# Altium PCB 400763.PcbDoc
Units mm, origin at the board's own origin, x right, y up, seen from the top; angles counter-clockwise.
Board outline 17.75 x 49.17 mm, 2 copper layers (Top Layer, Bottom Layer), stack 1.001 mm thick; 10 components, 18 nets, 81 pads, 135 vias.
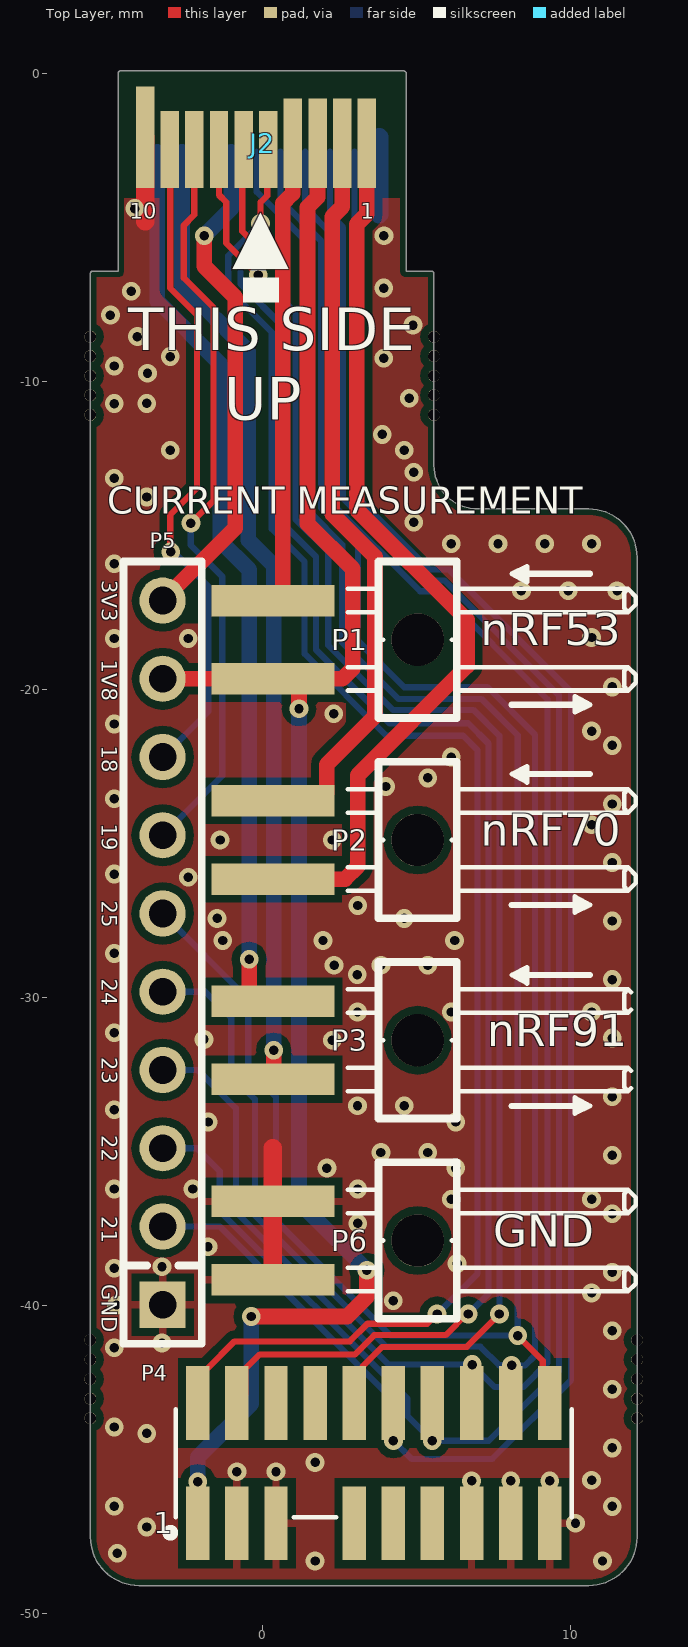
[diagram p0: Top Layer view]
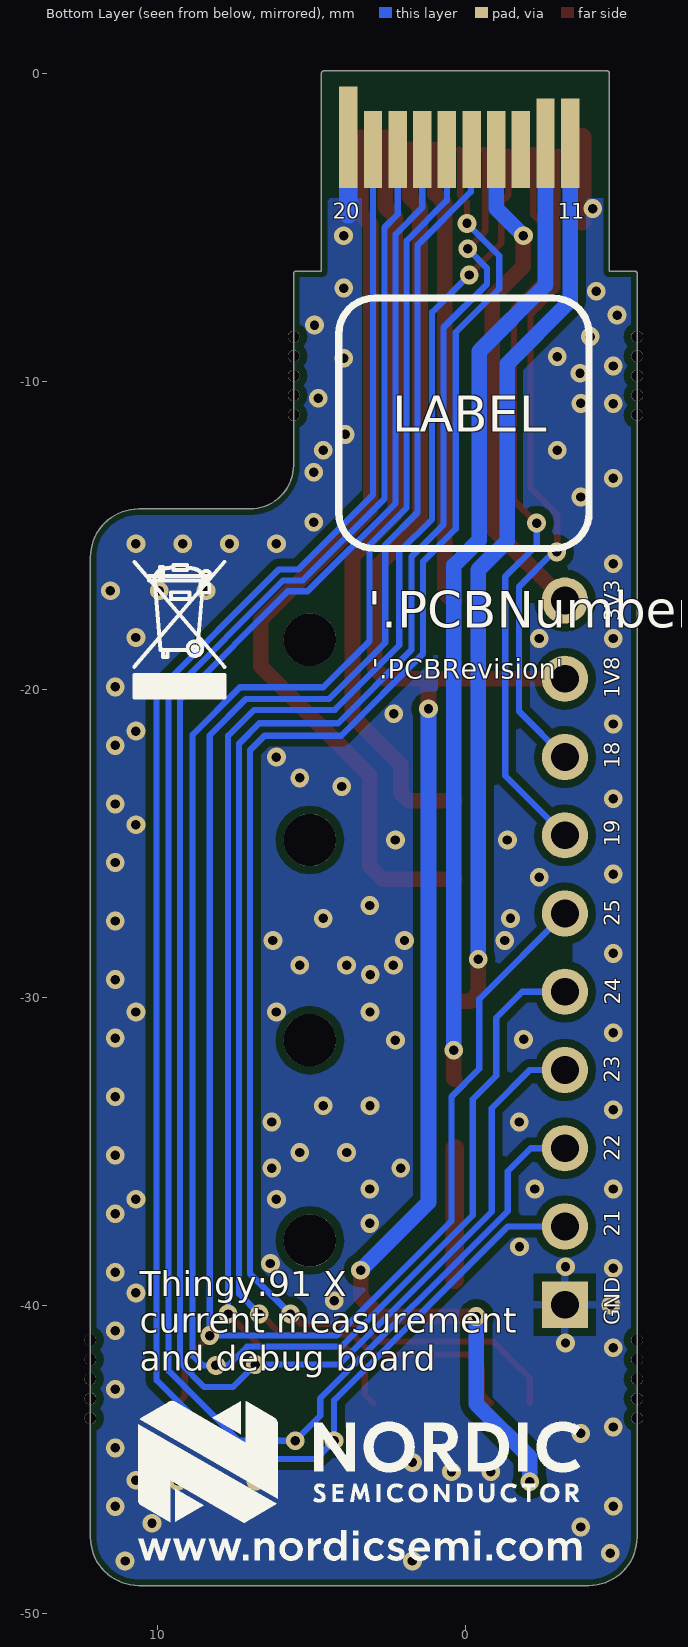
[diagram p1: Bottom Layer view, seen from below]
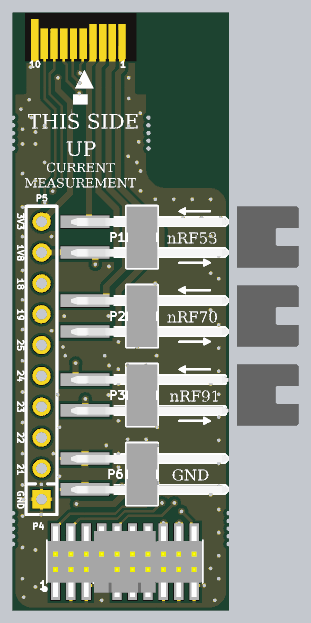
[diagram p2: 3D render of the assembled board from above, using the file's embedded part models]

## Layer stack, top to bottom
Top Solder: solder mask 0.0102, Solder Resist, Dk 3.5
Top Layer: signal copper 0.0356
Dielectric1: core 0.93, FR-4 Halogen Free, Dk 4.8
Bottom Layer: signal copper 0.0356
Bottom Solder: solder mask 0.0102, Solder Resist, Dk 3.5

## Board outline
-5.576,-47.526 -5.577,-12.025 -5.577,-6.5 cw(c-5.5,-6.5) -5.5,-6.423 -4.677,-6.423 -4.677,0 cw(c-4.6,0) -4.6,0.077 4.6,0.077 cw(c4.6,0) 4.677,0 4.677,-6.423 5.5,-6.423 cw(c5.5,-6.5) 5.577,-6.5 5.577,-12.744 5.576,-12.725 ccw(c7,-12.72) 6.995,-14.144 7,-14.143 10.606,-14.143 cw(c10.6,-15.72) 12.176,-15.714 12.177,-47.526 cw(c10.6,-47.52) 10.606,-49.096 10.591,-49.097 -4.006,-49.097 cw(c-4,-47.52)

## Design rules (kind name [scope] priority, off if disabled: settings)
BoardOutlineClearance [Not (HasPad('Free-666') OR OnTopSilkscreen)] p1: gap=0.2 ignorepadtopadclearanceinfootprint=FALSE
Clearance ANT_Clerance [InNet('ANT')] p1: gap=0.127 ignorepadtopadclearanceinfootprint=FALSE except(0: Arc-Hole Track-Hole SMDPad-Hole THPad-Hole Via-Hole Fill-Hole Poly-Hole Region-Hole Text-Hole)
Clearance Polygon_Clearance [(InNamedPolygon('Top_Layer-GND')) or (InNamedPolygon('Bottom_Layer-GND'))] p2: gap=0.254 ignorepadtopadclearanceinfootprint=FALSE
Clearance [All] p3: gap=0.152 ignorepadtopadclearanceinfootprint=FALSE except(0: Arc-Hole Track-Hole SMDPad-Hole THPad-Hole Via-Hole Fill-Hole Poly-Hole Region-Hole Text-Hole)
ComponentClearance [All] p1 off: gap=0.254 collisioncheckmode=3 verticalgap=0.254 showdistances=FALSE
DiffPairsRouting [All] p1: maxlimit=0.15 minlimit=0.15 mostfreqgap=0.15 toplayer_minwidth=0.381 toplayer_maxwidth=0.381 toplayer_prefwidth=0.381 bottomlayer_minwidth=0.381 bottomlayer_maxwidth=0.381 bottomlayer_prefwidth=0.381 maxuncoupledlength=12.7
FabricationTestPointUsage TestPointUsage [All] p1: valid=0 allowmultiple=FALSE
FabricationTestpoint Testpoint [All] p1: side=3 testpointundercomponent=TRUE minsize=1.016 maxsize=2.54 preferedsize=1.524 minholesize=0 maxholesize=1.016 preferedholesize=0.813 testpointgrid=0.025 allowsidetop=TRUE allowsidebottom=TRUE usegrid=TRUE gridtolerance=0
Height [All] p1 off: minheight=0 maxheight=25.4 prefheight=12.7
HoleSize [All] p1: absolutevalues=TRUE maxlimit=5 minlimit=0.305 maxpercent=80.000 minpercent=20.000
MinimumAnnularRing [All] p1 off: minimumring=0.152
PolygonConnect PolygonConnect_1 [isVia and innet(gnd)] p1: connectstyle=Direct reliefconductorwidth=0.254 reliefentries=4 polygonreliefangle="90 Angle" airgapwidth=0.254
PolygonConnect [All] p2: connectstyle=Relief reliefconductorwidth=0.254 reliefentries=4 polygonreliefangle="90 Angle" airgapwidth=0.254
RoutingVias [All] p1: holewidth=0.305 width=0.61 viastyle="Through Hole" minholewidth=0.305 minwidth=0.61 maxholewidth=0.305 maxwidth=0.61
SilkToSolderMaskClearance SilkscreenOverComponentPads [IsPad] p1: minsilkscreentomaskgap=0.125 clearancetoexposedcopper=TRUE
SolderMaskExpansion [All] p1: expansion=0.076 istentingtop=FALSE
Width [All] p1: maxlimit=2.54 minlimit=0.203 preferedwidth=0.381
23 further rules are at their usual default settings.

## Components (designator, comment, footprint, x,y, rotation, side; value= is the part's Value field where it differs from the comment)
J2 "Card Edge, 0.8mm" 10056847-101LF_Mating_Board_Thingy91_v2 0,0.075 r0 top locked
JP1 "Shunt 2.54mm" Shunt_2.54mm_Horizontal 15.4,-20.905 r90 top locked
JP2 "Shunt 2.54mm" Shunt_2.54mm_Horizontal 15.4,-27.407 r90 top locked
JP3 "Shunt 2.54mm" Shunt_2.54mm_Horizontal 15.4,-33.909 r90 top locked
P1 "Pin List 1x2, Angled" LIST_ANG_1x2-SMD-2.54MM 0.555,-18.39 r90 top locked
P2 "Pin List 1x2, Angled" LIST_ANG_1x2-SMD-2.54MM 0.555,-24.892 r90 top locked
P3 "Pin List 1x2, Angled" LIST_ANG_1x2-SMD-2.54MM 0.555,-31.395 r90 top locked
P4 "Pin Header 2x10, 1.27mm, SWD" HDR_2x10-SMD-1.27mm-K-SWD 3.625,-45.125 r0 top locked
P5 "Pin List 1x10" LIST_1x10-NC -3.23,-28.55 r90 top locked
P6 "Pin List 1x2, Angled" LIST_ANG_1x2-SMD-2.54MM 0.555,-37.897 r90 top locked

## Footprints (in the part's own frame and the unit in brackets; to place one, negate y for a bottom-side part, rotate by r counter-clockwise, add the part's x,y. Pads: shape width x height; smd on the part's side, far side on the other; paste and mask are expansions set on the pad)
10056847-101LF_Mating_Board_Thingy91_v2 [mm]
  rect 0.6x2.9 smd paste-1 mask+0.025: 1(3.4,-2.35) 2(2.6,-2.35) 3(1.8,-2.35) 4(1,-2.35)
  rect 0.6x2.5 smd paste-1 mask+0.025: 5(0.2,-2.55) 6(-0.6,-2.55) 7(-1.4,-2.55) 8(-2.2,-2.55) 9(-3,-2.55)
  rect 0.6x3.3 smd paste-1 mask+0.025: 10(-3.8,-2.15)
  rect 0.6x2.9 smd far side paste-1 mask+0.025: 11(-3.4,-2.35) 12(-2.6,-2.35)
  rect 0.6x2.5 smd far side paste-1 mask+0.025: 13(-1.8,-2.55) 14(-1,-2.55) 15(-0.2,-2.55) 16(0.6,-2.55) 17(1.4,-2.55) 18(2.2,-2.55) 19(3,-2.55)
  rect 0.6x3.3 smd far side paste-1 mask+0.025: 20(3.8,-2.15)
HDR_2x10-SMD-1.27mm-K-SWD [mm] "SMT MICRO HEADER, (1,27) .050\" Keying Shroud w/ pin 7 removed"
  rect 0.76x2.4 smd: 1(-5.715,-1.95) 2(-5.715,1.95) 3(-4.445,-1.95) 4(-4.445,1.95) 5(-3.175,-1.95) 6(-3.175,1.95) 8(-1.905,1.95) 9(-0.635,-1.95) 10(-0.635,1.95) 11(0.635,-1.95) 12(0.635,1.95) 13(1.905,-1.95) 14(1.905,1.95) 15(3.175,-1.95) 16(3.175,1.95) 17(4.445,-1.95) 18(4.445,1.95) 19(5.715,-1.95) 20(5.715,1.95)
  silkscreen extent -6.73,-2.38 6.43,1.75, body extent -6.35,-2.92 6.35,2.92, height 6.11
LIST_1x10-NC [mm] "Pin List, 2.54mm through hole"
  rect 1.5x1.5 hole 0.9: 1(-11.43,0)
  round 1.5 hole 0.9: 2(-8.89,0) 3(-6.35,0) 4(-3.81,0) 5(-1.27,0) 6(1.27,0) 7(3.81,0) 8(6.35,0) 9(8.89,0) 10(11.43,0)
  silkscreen extent -12.7,-1.27 12.7,1.27
LIST_ANG_1x2-SMD-2.54MM [mm] "Pin List, 2.54mm, Surface Mount, Angled"
  round 1.7 hole 1.7 unplated: 0(0,-4.496)
  rect 1.02x4 smd: 1(-1.27,0.204) 2(1.27,0.204)
  silkscreen extent -2.54,-11.58 2.54,-2.22, body extent -2.56,-11.61 2.52,1.35, height 3.03
Shunt_2.54mm_Horizontal [mm]
  body extent 0,-2.54 5.03,2.54, height 3.09

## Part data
J2: library part 10056847-101LF_Mating_Board_for_Thingy:91_v2, "0.8mm pitch, dual edge, right angle, SMD, card edge connector", Manufacturer=FCI, Manufacturer Part Number=10056847-101LF, Part number IPS=N.A., Part number NEMS=100500798
JP1 JP2 JP3: library part "SHUNT JUMPER 2.54mm Black Tin", "Shunt Jumper 2.54mm Black, open top", Manufacturer=WCON, Manufacturer Part Number=3710-6001OS0B05, Part number IPS=N.A., Part number NEMS=100500728
P1 P2 P3 P6: library part "Pin List Ang 1x2 SMD, 2.54mm", "Pin List 1x2, 2.54mm (100mil), Right Angled, SMD", Manufacturer=WCON, Manufacturer Part Number=1125B-1102S0Z135CR06, Part number IPS=N.A., Part number NEMS=100500354
P4: library part "Pin Header 2x10 SMD, 1.27mm, KS, SWD (Cabcon)", "Pin Header 2x10, 1.27mm (50mil), SMD, Keying Shroud, Removed Pin 7", Manufacturer=WCON, Manufacturer Part Number=3132-20MS0BK00R5, Part number IPS=N.A., Part number NEMS=100500841,100500280
P5: library part "Pin List 1x10, N.C.", "Pin List 1x10, 2.54mm (100mil)", Manufacturer=N.A., Part number NEMS=100500336

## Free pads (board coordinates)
  round 0.381 hole 0.381 unplated mask+0: 666(-5.576,-43.665) 666(-5.576,-43.03) 666(-5.576,-42.395) 666(-5.576,-41.76) 666(-5.576,-41.125) 666(-5.576,-11.09) 666(-5.576,-10.455) 666(-5.576,-9.82) 666(-5.576,-9.185) 666(-5.576,-8.55) 666(5.577,-11.09) 666(5.577,-10.455) 666(5.577,-9.82) 666(5.577,-9.185) 666(5.577,-8.55) 666(12.176,-43.665) 666(12.176,-43.03) 666(12.176,-42.395) 666(12.176,-41.76) 666(12.176,-41.125)

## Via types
v1: diameter 0.61, hole 0.305, Top Layer to Bottom Layer, tented both sides, 135 vias

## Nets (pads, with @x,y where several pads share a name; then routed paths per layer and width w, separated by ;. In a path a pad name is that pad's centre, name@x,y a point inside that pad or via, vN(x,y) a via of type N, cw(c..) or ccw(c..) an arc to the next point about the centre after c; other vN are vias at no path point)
3V3: J2.14 P5.10 | length 16.3
  Top Layer w0.508: P5.10 -0.873,-14.763 -0.873,-7.275 -1.882,-6.266 v1(-1.882,-5.275)
  Bottom Layer w0.508: v1(-1.882,-5.275) -1,-4.393 J2.14@-1,-2.55
GND: J2.10 J2.20 P4.3 P4.5 P4.15 P4.17 P4.19 P5.1 P6.1 P6.2 | length 9.5
  Top Layer w0.6: -3.8,-4.8 J2.10 ; P6.1 P6.2 0.351,-34.9
  Bottom Layer w0.6: 3.8,-4.575 J2.20
  other v1: 1.72,-48.3 11.05,-48.3 -4.7,-48.046 -3.742,-47.198 10.175,-47.075 -4.8,-46.525 11.368,-46.529 6.8,-45.7 8.07,-45.7 9.34,-45.7 10.698,-45.678 -0.82,-45.4 0.45,-45.4 1.72,-45.1 11.368,-44.628 -3.742,-44.158 -4.8,-43.95 11.368,-42.728 -4.8,-41.375 -3.25,-41.225 11.368,-40.827 -4.728,-39.99 4.26,-39.853 10.698,-39.598 11.368,-38.927 -4.8,-38.8 -3.25,-38.75 6.33,-38.643 -1.756,-38.098 3.105,-37.34 11.368,-37.026 6.138,-36.558 10.698,-36.558 -4.8,-36.225 -2.253,-36.225 3.105,-36.225 2.102,-35.546 6.289,-35.546 11.368,-35.126 3.858,-35.038 5.378,-35.038 -1.748,-34.048 6.289,-34.048 -4.8,-33.65 3.098,-33.518 4.618,-33.518 11.368,-33.225 2.274,-31.394 -1.889,-31.365 11.368,-31.325 -4.8,-31.15 3.098,-30.478 6.138,-30.478 10.698,-30.478 11.368,-29.425 3.087,-29.262 2.338,-28.958 3.858,-28.958 5.378,-28.958 -4.8,-28.575 -1.278,-28.157 1.977,-28.157 6.249,-28.157 11.368,-27.524 -1.462,-27.438 4.618,-27.438 3.105,-27.018 -2.4,-26.1 -4.8,-26 11.368,-25.624 -1.364,-24.892 2.274,-24.892 10.698,-24.398 11.368,-23.723 -4.8,-23.55 4.012,-23.155 5.378,-22.878 6.138,-22.2 11.368,-21.823 10.698,-21.358 -4.8,-21.125 2.326,-20.793 11.368,-19.922 -4.8,-18.35 -2.4,-18.35 10.698,-18.318 8.418,-16.798 9.938,-16.798 11.525,-16.798 -4.8,-15.925 6.138,-15.278 7.658,-15.278 9.178,-15.278 10.698,-15.278 4.925,-14.575 -3.742,-13.758 -4.8,-13.15 4.925,-12.95 -2.982,-12.238 4.618,-12.238 3.9,-11.725 -4.8,-10.725 -3.742,-10.718 4.775,-10.55 -3.72,-9.737 -4.8,-9.504 3.952,-9.253 -2.982,-9.198 -4.05,-8.55 4.9,-8.175 -4.925,-7.85 -4.25,-7.075 3.95,-6.975 3.954,-5.275 -4.132,-4.393
nRF53_VIN: J2.3 P1.1 P4.1 P5.9 | length 55.3
  Top Layer w0.508: P5.9 -0.298,-19.66 P1.1 P1.1@0.941,-19.66 ; v1(-0.355,-40.364) 2.762,-40.364 3.397,-39.729 3.397,-38.867 v1(3.403,-38.862) ; v1(1.197,-20.635) 1.197,-19.916 P1.1@0.941,-19.66 ; J2.3@1.8,-2.475 1.8,-4.025 1.474,-4.351 1.474,-14.624 2.939,-16.089 2.939,-19.326 2.605,-19.66 P1.1@0.941,-19.66
  Bottom Layer w0.508: P5.9@-3.13,-19.892 P5.9@-3.13,-19.66 ; v1(-2.09,-45.725) -2.09,-44.935 -0.355,-43.2 v1(-0.355,-40.364) ; v1(1.197,-20.635) 1.198,-36.656 v1(3.403,-38.862)
nRF53_VOUT: J2.4 P1.2 | length 15
  Top Layer w0.508: P1.2 0.418,-17.12 0.674,-16.864 0.674,-4.217 0.99,-3.901 0.99,-2.485 J2.4@1,-2.475
nRF70_VIN: J2.1 P2.1 | length 29.7
  Top Layer w0.508: P2.1 2.692,-26.162 3.105,-25.749 3.105,-22.789 6.65,-19.244 6.65,-17.75 3.074,-14.174 3.074,-4.901 3.4,-4.575 J2.1@3.4,-2.075
nRF70_VOUT: J2.2 P2.2 | length 24.5
  Top Layer w0.508: P2.2 1.841,-23.622 2.097,-23.366 2.097,-22.444 3.666,-20.875 3.666,-15.7 2.274,-14.308 2.274,-4.657 2.6,-4.332 J2.2@2.6,-2.075
nRF91_VIN: J2.12 P3.1 | length 31.4
  Top Layer w0.508: P3.1 0.375,-32.641 v1(0.375,-31.717)
  Bottom Layer w0.508: J2.12@-2.6,-2.55 -2.6,-6.874 -0.452,-9.022 -0.452,-15.152 0.375,-15.979 v1(0.375,-31.717)
nRF91_VOUT: J2.11 P3.2 | length 29.4
  Top Layer w0.508: v1(-0.42,-28.767) -0.42,-29.869 -0.164,-30.125 P3.2
  Bottom Layer w0.508: J2.11@-3.4,-2.55 -3.4,-7.396 -1.364,-9.433 -1.364,-15.174 -0.42,-16.118 v1(-0.42,-28.767)
P0.18: J2.9 P5.8 | length 21.6
  Top Layer w0.203: J2.9@-3.005,-2.539 -2.984,-2.56 -2.984,-6.975 -2.117,-7.842 -2.117,-13.469 -2.984,-14.336 -2.984,-15.524 v1(-2.968,-15.54)
  Bottom Layer w0.203: P5.8 -1.739,-20.709 -1.739,-16.666 -2.865,-15.54 v1(-2.968,-15.54)
P0.19: J2.8 P5.7 | length 24.3
  Top Layer w0.203: v1(-2.311,-14.605) -1.577,-13.871 -1.577,-7.616 -2.548,-6.644 -2.548,-4.941 -2.2,-4.593 J2.8
  Bottom Layer w0.203: P5.7 -1.296,-22.806 -1.296,-16.337 -2.316,-15.316 -2.316,-14.61 v1(-2.311,-14.605)
P0.21: J2.19 P4.12 P5.2 | length 61.4
  Bottom Layer w0.203: P5.2 -1.376,-37.44 4.263,-43.08 v1(4.263,-44.4) 4.849,-44.986 7.475,-44.986 10.027,-42.433 10.027,-20.078 6.058,-16.109 5.421,-16.109 3,-13.688 J2.19@3,-2.55
P0.22: J2.18 P4.14 P5.3 | length 61.9
  Bottom Layer w0.203: P5.3 -2.121,-34.9 -1.373,-35.648 -1.373,-36.941 4.71,-43.024 4.71,-43.585 v1(5.525,-44.4) 7.361,-44.4 9.636,-42.125 9.636,-20.19 5.911,-16.465 5.274,-16.465 2.627,-13.818 2.627,-5.006 2.2,-4.579 J2.18@2.2,-2.55
P0.23: J2.17 P4.16 P5.4 | length 62
  Bottom Layer w0.203: P5.4 -2.091,-32.36 -0.852,-33.599 -0.852,-36.959 4.114,-41.925 v1(6.825,-41.925) 7.553,-42.653 8.48,-42.653 9.264,-41.87 9.264,-20.32 5.764,-16.821 5.127,-16.821 2.266,-13.96 2.266,-5.223 1.4,-4.357 J2.17@1.4,-2.55
P0.24: J2.16 P4.18 P5.5 | length 64.6
  Bottom Layer w0.203: P5.5 -1.849,-29.82 -1.001,-30.668 -1.001,-32.546 -0.235,-33.313 -0.235,-37.073 4.031,-41.339 7.087,-41.339 7.694,-41.946 8.096,-41.946 v1(8.1,-41.95) 8.537,-41.95 8.858,-41.629 8.858,-21.476 7.319,-19.937 4.617,-19.937 3.113,-18.432 3.113,-15.309 1.91,-14.107 1.91,-5.434 0.6,-4.123 J2.16@0.6,-2.55
P0.25: J2.15 P4.20 P5.6 | length 67
  Top Layer w0.203: v1(8.299,-40.984) 9.113,-41.797 9.113,-42.948 P4.20
  Bottom Layer w0.203: P5.6 -0.452,-30.058 -0.452,-32.318 0.45,-33.22 0.45,-37.255 4.179,-40.984 v1(8.299,-40.984) 8.299,-21.489 7.123,-20.313 4.426,-20.313 2.603,-18.49 2.603,-15.309 1.555,-14.261 1.555,-5.581 -0.18,-3.846 -0.18,-2.57 J2.15@-0.2,-2.55
RESET: J2.7 P4.10 | length 49.5
  Top Layer w0.203: J2.7@-1.4,-2.55 -1.4,-3.951 -1.163,-4.189 -1.163,-5.512 v1(-0.125,-6.55) ; P4.10 3.268,-42.897 3.268,-41.984 3.901,-41.351 6.642,-41.351 7.705,-40.289 v1(7.705,-40.283)
  Bottom Layer w0.203: v1(-0.125,-6.55) 1.082,-7.757 1.082,-14.476 2.146,-15.54 2.146,-18.57 4.245,-20.67 6.862,-20.67 7.705,-21.512 v1(7.705,-40.283)
SWDCLK: J2.6 P4.4 | length 52.6
  Top Layer w0.203: P4.4 -0.542,-42.897 -0.542,-42.063 -0.071,-41.593 3.019,-41.593 3.644,-40.967 5.956,-40.967 v1@6.692,-40.231 ; J2.6 -0.646,-2.521 -0.646,-5.129 v1(-0.075,-5.7)
  Bottom Layer w0.203: v1(-0.075,-5.7) -0.7,-6.325 -0.7,-6.844 0.711,-8.255 0.711,-14.654 1.749,-15.693 1.749,-18.716 4.135,-21.102 6.691,-21.102 7.349,-21.76 7.349,-39.626 v1(6.692,-40.283)
SWDIO: J2.5 P4.2 | length 53.1
  Top Layer w0.203: P4.2 -2.09,-42.355 -1.812,-42.077 -1.801,-42.077 -0.897,-41.172 2.848,-41.172 3.422,-40.599 5.363,-40.599 v1(5.68,-40.283) ; v1(-0.05,-4.875) -0.05,-4.189 0.166,-3.973 0.166,-2.509 J2.5
  Bottom Layer w0.203: v1(-0.05,-4.875) -1.097,-5.922 -1.097,-7.002 0.313,-8.412 0.313,-14.793 1.378,-15.858 1.378,-18.852 4.034,-21.509 6.524,-21.509 6.993,-21.978 6.993,-38.969 v1(5.68,-40.283)
pads on no net: J2.13 P1.0 P2.0 P3.0 P4.6 P4.8 P4.9 P4.11 P4.13 P6.0

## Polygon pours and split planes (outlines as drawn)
GND on Bottom Layer "Bottom_Layer-GND" (solid, remove dead copper, pour order 53): -5.576,-47.526 -5.577,-12.025 -5.577,-6.5 cw(c-5.5,-6.5) -5.5,-6.423 -4.677,-6.423 -4.677,0 cw(c-4.6,0) -4.6,0.077 4.6,0.077 cw(c4.6,0) 4.677,0 4.677,-6.423 5.5,-6.423 cw(c5.5,-6.5) 5.577,-6.5 5.577,-12.744 5.576,-12.725 ccw(c7,-12.72) 6.995,-14.144 7,-14.143 10.606,-14.143 cw(c10.6,-15.72) 12.176,-15.714 12.177,-47.526 cw(c10.6,-47.52) 10.606,-49.096 10.591,-49.097 -4.006,-49.097 cw(c-4,-47.52)
GND on Top Layer "Top_Layer-GND" (solid, remove dead copper, pour order 52): -5.576,-47.526 -5.577,-12.025 -5.577,-6.5 cw(c-5.5,-6.5) -5.5,-6.423 -4.677,-6.423 -4.677,0 cw(c-4.6,0) -4.6,0.077 4.6,0.077 cw(c4.6,0) 4.677,0 4.677,-6.423 5.5,-6.423 cw(c5.5,-6.5) 5.577,-6.5 5.577,-12.744 5.576,-12.725 ccw(c7,-12.72) 6.995,-14.144 7,-14.143 10.606,-14.143 cw(c10.6,-15.72) 12.176,-15.714 12.177,-47.526 cw(c10.6,-47.52) 10.606,-49.096 10.591,-49.097 -4.006,-49.097 cw(c-4,-47.52)

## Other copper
Top Layer:
  pour cut-out: -1.577,-17.773 -2.656,-17.773 -2.656,-17.876 -1.577,-17.876
  pour cut-out: -1.898,-17.816 -1.898,-18.896 -1.795,-18.896 -1.795,-17.816
  pour cut-out: 2.722,-20.162 2.722,-21.114 2.825,-21.114 2.825,-20.162
  pour cut-out: -4.925,-4.054 4.654,-4.054 4.654,0.35 -4.925,0.35
Bottom Layer:
  pour cut-out: -3.285,-28.258 -3.285,-28.842 -3.492,-28.842 -3.492,-28.258
  pour cut-out: 4.925,-4.054 -5.115,-4.054 -5.115,0.325 4.925,0.325

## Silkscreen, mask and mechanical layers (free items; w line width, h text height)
Top Overlay:
  rectangle: -0.619,-7.45 0.556,-6.625
  lines w0.15: 8.35,-29.275 8.6,-29.525 8.6,-29.025 8.1,-29.275 8.6,-29.55 ; 8.35,-22.75 8.6,-23 8.6,-22.5 8.1,-22.75 8.6,-23.025 ; 8.35,-16.25 8.6,-16.5 8.6,-16 8.1,-16.25 8.6,-16.525 ; 8.45,-29.125 8.55,-29.425 ; 8.45,-22.6 8.55,-22.9 ; 8.45,-16.1 8.55,-16.4 ; 10.15,-33.25 10.65,-33.525 10.15,-33.775 10.15,-33.275 10.4,-33.525 ; 10.15,-26.725 10.65,-27 10.15,-27.25 10.15,-26.75 10.4,-27 ; 10.15,-20.225 10.65,-20.5 10.15,-20.75 10.15,-20.25 10.4,-20.5 ; 10.2,-33.375 10.3,-33.675 ; 10.2,-26.85 10.3,-27.15 ; 10.2,-20.35 10.3,-20.65
  lines w0.2: 8.1,-33.525 8.875,-33.525 ; 8.1,-27 8.875,-27 ; 8.1,-20.5 8.875,-20.5 ; 8.35,-29.275 9.85,-29.275 ; 8.35,-22.75 9.85,-22.75 ; 8.35,-16.25 9.85,-16.25 ; 8.9,-33.525 10.4,-33.525 ; 8.9,-27 10.4,-27 ; 8.9,-20.5 10.4,-20.5 ; 9.875,-29.275 10.65,-29.275 ; 9.875,-22.75 10.65,-22.75 ; 9.875,-16.25 10.65,-16.25
  text "▲" at -0.963,-6.65 h3
  text "THIS SIDE" at -4.351,-9.45 h2.36
  text "UP" at -1.232,-11.7 h2.36
  text "CURRENT MEASUREMENT" at -5.032,-14.6 h1.5
  text "3V3" at -5.21,-16.454 h0.5 r270
  text "nRF53" at 7.1,-18.914 h1.78
  text "1V8" at -5.21,-19.035 h0.5 r270
  text "18" at -5.21,-21.825 h0.5 r270
  text "19" at -5.21,-24.365 h0.5 r270
  text "nRF70" at 7.106,-25.416 h1.78
  text "25" at -5.21,-26.863 h0.5 r270
  text "24" at -5.21,-29.403 h0.5 r270
  text "nRF91" at 7.309,-31.93 h1.78
  text "23" at -5.21,-31.943 h0.5 r270
  text "22" at -5.21,-34.483 h0.5 r270
  text "21" at -5.21,-37.107 h0.5 r270
  text "GND" at 7.5,-38.432 h1.78
  text "GND" at -5.21,-39.314 h0.5 r270
  text "1" at -3.523,-47.398 h0.69
Bottom Overlay:
  drawing of 880 lines, arcs and shapes, not listed
  text "LABEL" at 2.375,-12.025 h2
  text "3V3" at -5.01,-17.786 h0.5 r270
  text "'.PCBNumber'" at 3.174,-18.391 h2.03
  text "'.PCBRevision'" at 3.047,-19.65 h0.64
  text "1V8" at -5.01,-20.285 h0.5 r270
  text "18" at -5.01,-22.575 h0.5 r270
  text "19" at -5.01,-25.115 h0.5 r270
  text "25" at -5.01,-27.697 h0.5 r270
  text "24" at -5.035,-30.237 h0.5 r270
  text "23" at -5.01,-32.777 h0.5 r270
  text "22" at -5.01,-35.317 h0.5 r270
  text "21" at -5.01,-37.773 h0.5 r270
  text "Thingy:91 X" at 10.572,-39.984 h1.4
  text "GND" at -5.01,-40.646 h0.5 r270
  text "current measurement" at 10.572,-41.171 h1.4
  text "and debug board" at 10.572,-42.398 h1.4
Top Paste:
  text "↑" at -0.925,-8.575 h0.89
Board Outline:
  lines w0.127: -5.577,-47.526 -5.577,-12.025 -5.577,-6.52 ; -5.577,-6.5 cw(c-5.5,-6.5) -5.5,-6.423 -4.677,-6.423 -4.677,0 cw(c-4.6,0) -4.6,0.077 4.6,0.077 cw(c4.6,0) 4.677,0 4.677,-6.423 5.5,-6.423 cw(c5.5,-6.5) 5.577,-6.5 ; -5.576,-47.526 ccw(c-4,-47.52) -4.006,-49.096 10.591,-49.097 ; -3.006,-49.096 ccw(c-3,-49.02) -3,-49.097 ; 5.577,-12.744 5.577,-6.52 ; 5.576,-12.725 ccw(c7,-12.72) 6.995,-14.144 ; 7,-14.143 10.606,-14.143 cw(c10.6,-15.72) 12.176,-15.714 12.177,-47.526 cw(c10.6,-47.52) 10.606,-49.096 ; 12.176,-45.526 ccw(c12.1,-45.52) 12.177,-45.52 ; 12.177,-20.02 ccw(c12.1,-20.02) 12.176,-20.014
Route Tool Path:
  lines w1.6: -6.406,-8.325 -6.377,-6.5 ; -6.377,-11.3 -6.376,-40.825 ; -6.376,-43.875 -6.376,-47.526 ccw(c-5.576,-47.526) -6.376,-47.529 ccw(c-4,-47.52) -4.009,-49.897 ; -5.477,-4.098 -5.477,1.525 ; -5.477,1.532 cw(c-4.6,1.525) -4.607,2.402 ; -4.6,2.402 4.6,2.402 ; 4.607,2.402 cw(c4.6,1.525) 5.477,1.532 ; 5.477,-4.098 5.477,1.525 ; 6.377,-11.3 6.377,-12.736 ; 6.377,-8.3 6.377,-6.5 ; 10.617,-49.896 ccw(c10.6,-47.52) 12.977,-47.531 ; 12.977,-43.875 12.977,-47.531 ; 12.977,-40.875 12.976,-15.714 ; -6.377,-6.5 cw(c-5.577,-6.5) -6.377,-6.493 ; -6.377,-6.5 cw(c-5.5,-6.5) -6.377,-6.493 ; -6.377,-6.493 cw(c-5.5,-6.5) -5.507,-5.623 ; -5.507,-5.623 cw(c-5.5,-6.5) -5.5,-5.623 ; -5.507,-5.623 cw(c-5.5,-6.423) -5.5,-5.623 ; -5.5,-5.623 -5.477,-5.623 -5.477,0 ; -5.477,0 cw(c-4.6,0) -5.477,0.007 ; -5.477,0 cw(c-4.677,0) -5.477,0.007 ; -5.477,0.007 cw(c-4.6,0) -4.607,0.877 ; -4.607,0.877 cw(c-4.6,0.077) -4.6,0.877 ; -4.607,0.877 cw(c-4.6,0) -4.6,0.877 ; -4.6,0.877 4.6,0.877 ; -4.009,-49.897 ccw(c-4.006,-49.097) -4.006,-49.897 ; -4.009,-49.897 ccw(c-4.006,-49.097) -4.006,-49.897 ; -4.006,-49.897 10.591,-49.897 ; -4.006,-49.897 -4.006,-49.897 ; 4.6,0.877 cw(c4.6,0) 4.607,0.877 ; 4.6,0.877 cw(c4.6,0.077) 4.607,0.877 ; 4.607,0.877 cw(c4.6,0) 5.477,0.007 ; 5.477,0 ccw(c4.6,0) 5.477,0.007 ; 5.477,0 ccw(c4.677,0) 5.477,0.007 ; 5.477,0 5.477,-5.623 5.5,-5.623 ; 5.5,-5.623 cw(c5.5,-6.423) 5.507,-5.623 ; 5.5,-5.623 cw(c5.5,-6.5) 5.507,-5.623 ; 5.507,-5.623 cw(c5.5,-6.5) 6.377,-6.493 ; 6.377,-12.736 ccw(c7,-12.72) 6.988,-13.343 ; 6.377,-12.736 ccw(c7,-12.72) 6.377,-12.736 ; 6.377,-6.5 ccw(c5.577,-6.5) 6.377,-6.493 ; 6.377,-6.5 ccw(c5.5,-6.5) 6.377,-6.493 ; 6.988,-13.343 cw(c7,-14.143) 7,-13.343 ; 6.988,-13.343 cw(c7,-14.143) 7,-13.343 ; 7,-13.343 10.606,-13.343 ; 10.591,-49.897 ccw(c10.591,-49.097) 10.602,-49.897 cw(c10.591,-49.097) 10.591,-49.897 ; 10.606,-13.343 cw(c10.606,-14.143) 10.611,-13.343 ; 10.606,-13.343 cw(c10.606,-14.143) 10.609,-13.343 cw(c10.6,-15.72) 10.611,-13.343 ; 10.611,-13.343 cw(c10.6,-15.72) 12.976,-15.711 ; 12.977,-47.531 ccw(c12.177,-47.526) 12.977,-47.526 cw(c12.177,-47.526) 12.977,-47.529 cw(c10.6,-47.52) 12.977,-47.531 ; 12.976,-15.714 ccw(c12.176,-15.714) 12.976,-15.711 ; 12.976,-15.714 ccw(c12.176,-15.714) 12.976,-15.711

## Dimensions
-4.6,0.077 to 1.575,-49.1 on Dimension
-5.576,-47.526 to 12.18,-47.314 on Dimension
